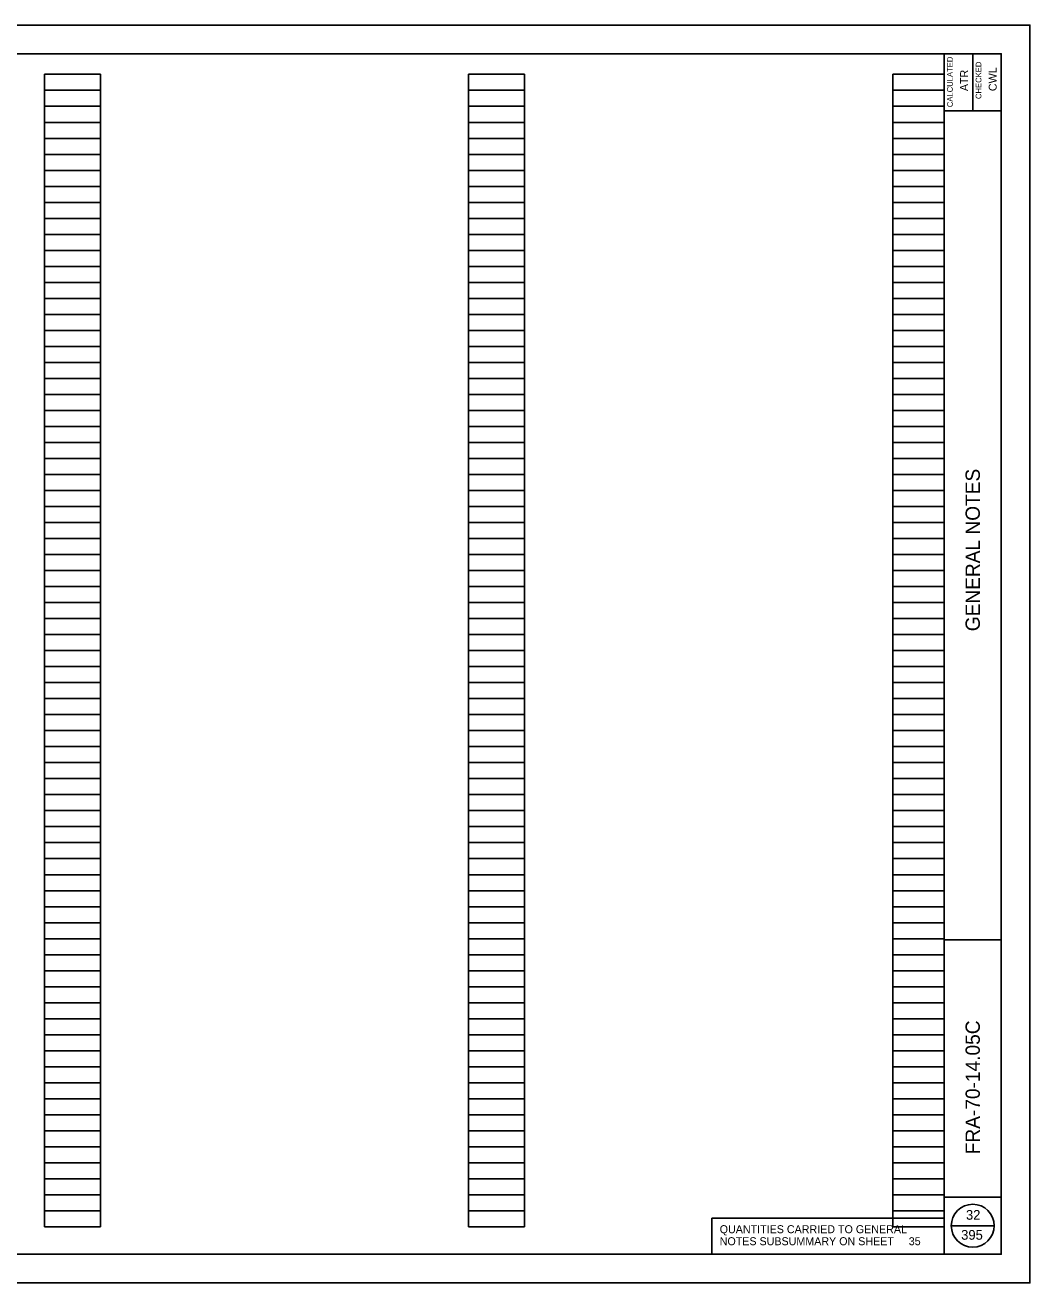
# Model space of a CAD drawing. Extents: x 0 to 34, y 0 to 22.
# Drawn here: x 16.42 to 34, y 0 to 22 of the extents above; entities that cross this region are included whole.
import ezdxf

# ---------------------------------------------------------------- set-up
doc = ezdxf.new("R2010")
doc.units = 0
for name, color, linetype in [('SC_Scratch1', 7, 'Continuous'), ('SH_Border', 7, 'Continuous'), ('SH_Cut_Line', 7, 'Continuous'), ('SH_Data', 7, 'Continuous'), ('TX_P_1', 7, 'Continuous')]:
    doc.layers.add(name, color=color, linetype=linetype)

msp = doc.modelspace()

# ---------------------------------------------------------------- linework, layer by layer
at = {"layer": 'SC_Scratch1'}
for p, q in [((16.76, 0.98), (16.76, 21.14)), ((16.76, 21.14), (17.74, 21.14)), ((17.74, 0.98), (17.74, 21.14)), ((24.18, 0.98), (24.18, 21.14)), ((24.18, 21.14), (25.16, 21.14)), ((25.16, 0.98), (25.16, 21.14)), ((31.6, 0.98), (31.6, 21.14)), ((31.6, 21.14), (32.5, 21.14)), ((32.5, 0.98), (32.5, 21.14)), ((16.76, 20.86), (17.74, 20.86)), ((24.18, 20.86), (25.16, 20.86)), ((31.6, 20.86), (32.5, 20.86)), ((16.76, 20.58), (17.74, 20.58)), ((24.18, 20.58), (25.16, 20.58)), ((31.6, 20.58), (32.5, 20.58)), ((16.76, 20.3), (17.74, 20.3)), ((24.18, 20.3), (25.16, 20.3)), ((31.6, 20.3), (32.5, 20.3)), ((16.76, 20.02), (17.74, 20.02)), ((24.18, 20.02), (25.16, 20.02)), ((31.6, 20.02), (32.5, 20.02)), ((16.76, 19.74), (17.74, 19.74)), ((24.18, 19.74), (25.16, 19.74)), ((31.6, 19.74), (32.5, 19.74)), ((16.76, 19.46), (17.74, 19.46)), ((24.18, 19.46), (25.16, 19.46)), ((31.6, 19.46), (32.5, 19.46)), ((16.76, 19.18), (17.74, 19.18)), ((24.18, 19.18), (25.16, 19.18)), ((31.6, 19.18), (32.5, 19.18)), ((16.76, 18.9), (17.74, 18.9)), ((24.18, 18.9), (25.16, 18.9)), ((31.6, 18.9), (32.5, 18.9)), ((16.76, 18.62), (17.74, 18.62)), ((24.18, 18.62), (25.16, 18.62)), ((31.6, 18.62), (32.5, 18.62)), ((16.76, 18.34), (17.74, 18.34)), ((24.18, 18.34), (25.16, 18.34)), ((31.6, 18.34), (32.5, 18.34)), ((16.76, 18.06), (17.74, 18.06)), ((24.18, 18.06), (25.16, 18.06)), ((31.6, 18.06), (32.5, 18.06)), ((16.76, 17.78), (17.74, 17.78)), ((24.18, 17.78), (25.16, 17.78)), ((31.6, 17.78), (32.5, 17.78)), ((16.76, 17.5), (17.74, 17.5)), ((24.18, 17.5), (25.16, 17.5)), ((31.6, 17.5), (32.5, 17.5)), ((16.76, 17.22), (17.74, 17.22)), ((24.18, 17.22), (25.16, 17.22)), ((31.6, 17.22), (32.5, 17.22)), ((16.76, 16.94), (17.74, 16.94)), ((24.18, 16.94), (25.16, 16.94)), ((31.6, 16.94), (32.5, 16.94)), ((16.76, 16.66), (17.74, 16.66)), ((24.18, 16.66), (25.16, 16.66)), ((31.6, 16.66), (32.5, 16.66)), ((16.76, 16.38), (17.74, 16.38)), ((24.18, 16.38), (25.16, 16.38)), ((31.6, 16.38), (32.5, 16.38)), ((16.76, 16.1), (17.74, 16.1)), ((24.18, 16.1), (25.16, 16.1)), ((31.6, 16.1), (32.5, 16.1)), ((16.76, 15.82), (17.74, 15.82)), ((24.18, 15.82), (25.16, 15.82)), ((31.6, 15.82), (32.5, 15.82)), ((16.76, 15.54), (17.74, 15.54)), ((24.18, 15.54), (25.16, 15.54)), ((31.6, 15.54), (32.5, 15.54)), ((16.76, 15.26), (17.74, 15.26)), ((24.18, 15.26), (25.16, 15.26)), ((31.6, 15.26), (32.5, 15.26)), ((16.76, 14.98), (17.74, 14.98)), ((24.18, 14.98), (25.16, 14.98)), ((31.6, 14.98), (32.5, 14.98)), ((16.76, 14.7), (17.74, 14.7)), ((24.18, 14.7), (25.16, 14.7)), ((31.6, 14.7), (32.5, 14.7)), ((16.76, 14.42), (17.74, 14.42)), ((24.18, 14.42), (25.16, 14.42)), ((31.6, 14.42), (32.5, 14.42)), ((16.76, 14.14), (17.74, 14.14)), ((24.18, 14.14), (25.16, 14.14)), ((31.6, 14.14), (32.5, 14.14)), ((16.76, 13.86), (17.74, 13.86)), ((24.18, 13.86), (25.16, 13.86)), ((31.6, 13.86), (32.5, 13.86)), ((16.76, 13.58), (17.74, 13.58)), ((24.18, 13.58), (25.16, 13.58)), ((31.6, 13.58), (32.5, 13.58)), ((16.76, 13.3), (17.74, 13.3)), ((24.18, 13.3), (25.16, 13.3)), ((31.6, 13.3), (32.5, 13.3)), ((16.76, 13.02), (17.74, 13.02)), ((24.18, 13.02), (25.16, 13.02)), ((31.6, 13.02), (32.5, 13.02)), ((16.76, 12.74), (17.74, 12.74)), ((24.18, 12.74), (25.16, 12.74)), ((31.6, 12.74), (32.5, 12.74)), ((16.76, 12.46), (17.74, 12.46)), ((24.18, 12.46), (25.16, 12.46)), ((31.6, 12.46), (32.5, 12.46)), ((16.76, 12.18), (17.74, 12.18)), ((24.18, 12.18), (25.16, 12.18)), ((31.6, 12.18), (32.5, 12.18)), ((16.76, 11.9), (17.74, 11.9)), ((24.18, 11.9), (25.16, 11.9)), ((31.6, 11.9), (32.5, 11.9)), ((16.76, 11.62), (17.74, 11.62)), ((24.18, 11.62), (25.16, 11.62)), ((31.6, 11.62), (32.5, 11.62)), ((16.76, 11.34), (17.74, 11.34)), ((24.18, 11.34), (25.16, 11.34)), ((31.6, 11.34), (32.5, 11.34)), ((16.76, 11.06), (17.74, 11.06)), ((24.18, 11.06), (25.16, 11.06)), ((31.6, 11.06), (32.5, 11.06)), ((16.76, 10.78), (17.74, 10.78)), ((24.18, 10.78), (25.16, 10.78)), ((31.6, 10.78), (32.5, 10.78)), ((16.76, 10.5), (17.74, 10.5)), ((24.18, 10.5), (25.16, 10.5)), ((31.6, 10.5), (32.5, 10.5)), ((16.76, 10.22), (17.74, 10.22)), ((24.18, 10.22), (25.16, 10.22)), ((31.6, 10.22), (32.5, 10.22)), ((16.76, 9.94), (17.74, 9.94)), ((24.18, 9.94), (25.16, 9.94)), ((31.6, 9.94), (32.5, 9.94)), ((16.76, 9.66), (17.74, 9.66)), ((24.18, 9.66), (25.16, 9.66)), ((31.6, 9.66), (32.5, 9.66)), ((16.76, 9.38), (17.74, 9.38)), ((24.18, 9.38), (25.16, 9.38)), ((31.6, 9.38), (32.5, 9.38)), ((16.76, 9.1), (17.74, 9.1)), ((24.18, 9.1), (25.16, 9.1)), ((31.6, 9.1), (32.5, 9.1)), ((16.76, 8.82), (17.74, 8.82)), ((24.18, 8.82), (25.16, 8.82)), ((31.6, 8.82), (32.5, 8.82)), ((16.76, 8.54), (17.74, 8.54)), ((24.18, 8.54), (25.16, 8.54)), ((31.6, 8.54), (32.5, 8.54)), ((16.76, 8.26), (17.74, 8.26)), ((24.18, 8.26), (25.16, 8.26)), ((31.6, 8.26), (32.5, 8.26)), ((16.76, 7.98), (17.74, 7.98)), ((24.18, 7.98), (25.16, 7.98)), ((31.6, 7.98), (32.5, 7.98)), ((16.76, 7.7), (17.74, 7.7)), ((24.18, 7.7), (25.16, 7.7)), ((31.6, 7.7), (32.5, 7.7)), ((16.76, 7.42), (17.74, 7.42)), ((24.18, 7.42), (25.16, 7.42)), ((31.6, 7.42), (32.5, 7.42)), ((16.76, 7.14), (17.74, 7.14)), ((24.18, 7.14), (25.16, 7.14)), ((31.6, 7.14), (32.5, 7.14)), ((16.76, 6.86), (17.74, 6.86)), ((24.18, 6.86), (25.16, 6.86)), ((31.6, 6.86), (32.5, 6.86)), ((16.76, 6.58), (17.74, 6.58)), ((24.18, 6.58), (25.16, 6.58)), ((31.6, 6.58), (32.5, 6.58)), ((16.76, 6.3), (17.74, 6.3)), ((24.18, 6.3), (25.16, 6.3)), ((31.6, 6.3), (32.5, 6.3)), ((16.76, 6.02), (17.74, 6.02)), ((24.18, 6.02), (25.16, 6.02)), ((31.6, 6.02), (32.5, 6.02)), ((16.76, 5.74), (17.74, 5.74)), ((24.18, 5.74), (25.16, 5.74)), ((31.6, 5.74), (32.5, 5.74)), ((16.76, 5.46), (17.74, 5.46)), ((24.18, 5.46), (25.16, 5.46)), ((31.6, 5.46), (32.5, 5.46)), ((16.76, 5.18), (17.74, 5.18)), ((24.18, 5.18), (25.16, 5.18)), ((31.6, 5.18), (32.5, 5.18)), ((16.76, 4.9), (17.74, 4.9)), ((24.18, 4.9), (25.16, 4.9)), ((31.6, 4.9), (32.5, 4.9)), ((16.76, 4.62), (17.74, 4.62)), ((24.18, 4.62), (25.16, 4.62)), ((31.6, 4.62), (32.5, 4.62)), ((16.76, 4.34), (17.74, 4.34)), ((24.18, 4.34), (25.16, 4.34)), ((31.6, 4.34), (32.5, 4.34)), ((16.76, 4.06), (17.74, 4.06)), ((24.18, 4.06), (25.16, 4.06)), ((31.6, 4.06), (32.5, 4.06)), ((16.76, 3.78), (17.74, 3.78)), ((24.18, 3.78), (25.16, 3.78)), ((31.6, 3.78), (32.5, 3.78)), ((16.76, 3.5), (17.74, 3.5)), ((24.18, 3.5), (25.16, 3.5)), ((31.6, 3.5), (32.5, 3.5)), ((16.76, 3.22), (17.74, 3.22)), ((24.18, 3.22), (25.16, 3.22)), ((31.6, 3.22), (32.5, 3.22)), ((16.76, 2.94), (17.74, 2.94)), ((24.18, 2.94), (25.16, 2.94)), ((31.6, 2.94), (32.5, 2.94)), ((16.76, 2.66), (17.74, 2.66)), ((24.18, 2.66), (25.16, 2.66)), ((31.6, 2.66), (32.5, 2.66)), ((16.76, 2.38), (17.74, 2.38)), ((24.18, 2.38), (25.16, 2.38)), ((31.6, 2.38), (32.5, 2.38)), ((16.76, 2.1), (17.74, 2.1)), ((24.18, 2.1), (25.16, 2.1)), ((31.6, 2.1), (32.5, 2.1)), ((16.76, 1.82), (17.74, 1.82)), ((24.18, 1.82), (25.16, 1.82)), ((31.6, 1.82), (32.5, 1.82)), ((16.76, 1.54), (17.74, 1.54)), ((24.18, 1.54), (25.16, 1.54)), ((31.6, 1.54), (32.5, 1.54)), ((16.76, 1.26), (17.74, 1.26)), ((24.18, 1.26), (25.16, 1.26)), ((31.6, 1.26), (32.5, 1.26)), ((16.76, 0.98), (17.74, 0.98)), ((24.18, 0.98), (25.16, 0.98)), ((31.6, 0.98), (32.5, 0.98))]:
    msp.add_line(p, q, dxfattribs=at)
at = {"layer": 'SH_Border'}
for p, q in [((32.5, 0.5), (32.5, 21.5)), ((33, 21.5), (33, 20.5)), ((32.5, 20.5), (33.5, 20.5)), ((32.5, 6), (33.5, 6)), ((32.5, 1.5), (33.5, 1.5))]:
    msp.add_line(p, q, dxfattribs=at)
msp.add_lwpolyline([(2, 21.5), (33.5, 21.5), (33.5, 0.5), (2, 0.5)], close=True, dxfattribs=at)
at = {"layer": 'SH_Cut_Line'}
msp.add_lwpolyline([(0, 0), (34, 0), (34, 22), (0, 22)], close=True, dxfattribs=at)
at = {"layer": 'SH_Data'}
msp.add_line((32.625, 1), (33.375, 1), dxfattribs=at)
msp.add_circle((33, 1), 0.375, dxfattribs=at)
at = {"layer": 'TX_P_1'}
msp.add_lwpolyline([(28.437, 1.132), (32.5, 1.132), (32.5, 0.5), (28.437, 0.5)], close=True, dxfattribs=at)

# ---------------------------------------------------------------- texts
at = {"layer": 'SH_Data'}
for s, height, p in [('CALCULATED', 0.1, (32.652, 20.565)), ('CHECKED', 0.1, (33.152, 20.708)), ('ATR', 0.14, (32.92, 20.846)), ('CWL', 0.14, (33.42, 20.846)), ('GENERAL NOTES', 0.25, (33.125, 11.398)), ('FRA-70-14.05C', 0.25, (33.125, 2.249))]:
    msp.add_text(s, height=height, rotation=90, dxfattribs=at).set_placement(p)
for s, p in [('32', (32.882, 1.104)), ('395', (32.798, 0.754))]:
    msp.add_text(s, height=0.17, dxfattribs=at).set_placement(p)
at = {"layer": 'TX_P_1'}
for s, p in [('QUANTITIES CARRIED TO GENERAL', (28.573, 0.868)), ('NOTES SUBSUMMARY ON SHEET', (28.573, 0.658)), ('35', (31.881, 0.658))]:
    msp.add_text(s, height=0.14, dxfattribs=at).set_placement(p)

doc.saveas('drawing.dxf')
